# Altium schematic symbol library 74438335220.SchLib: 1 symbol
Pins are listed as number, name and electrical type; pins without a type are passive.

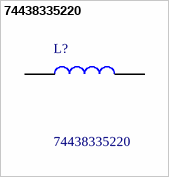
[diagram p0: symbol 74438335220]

## 74438335220
designator L?
Power Inductor (SMD), 22 H, 600 mA, Shielded, 1.6 A, WE-MAPI, 3mm x 3mm x 1.5mm; Manufacturer_Name: Wurth Elektronik
footprint 74438335220
pins: 1, 2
